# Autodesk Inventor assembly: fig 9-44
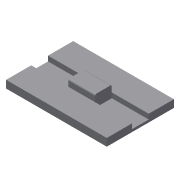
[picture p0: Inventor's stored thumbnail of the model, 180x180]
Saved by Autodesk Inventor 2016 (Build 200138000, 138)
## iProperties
Created: 2013-07
Part Number: fig 9-44
Document SubType Name: Assembly
Designer: CADCIM
Author: CADCIM
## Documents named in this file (3)
- D:\KAVITA\Autodesk Inventor_ 2016 Project_Kavita\Inventor_Part Files\Inventor_2016_Part\c09_Inv_2016\c09_inv_2016_prt\fig 9-44.iam
- D:\KAVITA\Autodesk Inventor_ 2016 Project_Kavita\Inventor_Part Files\Inventor_2016_Part\c09_Inv_2016\c09_inv_2016_prt\15.ipt
- D:\KAVITA\Autodesk Inventor_ 2016 Project_Kavita\Inventor_Part Files\Inventor_2016_Part\c09_Inv_2016\c09_inv_2016_prt\16.ipt
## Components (2 placed, 2 different names)
1. 15:1 — Slider:1
2. 16:1 — Slider:1
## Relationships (1: TranslationJoint 1)
- Slider:1 [TranslationJoint]: 15:1 ↔ 16:1
